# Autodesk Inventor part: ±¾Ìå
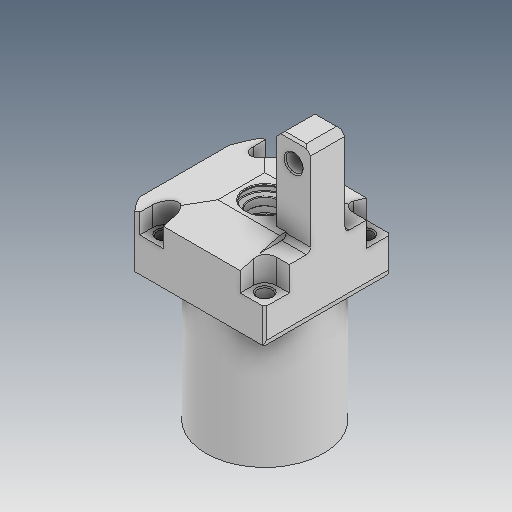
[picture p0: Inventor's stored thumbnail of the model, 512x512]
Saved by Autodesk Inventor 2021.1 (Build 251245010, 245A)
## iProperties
Created: 2013-04
Part Number: ±¾Ìå
Material: Ogólny
Document SubType Name: Modeling
Designer: user
Density: 1 g/cm^3
Appearance: Domyślna
Author: user
Revision Number: ÈÎºÎ
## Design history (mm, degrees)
feature "ÇÐ³ý-É¨Ãè22"
node "Bryła1"
